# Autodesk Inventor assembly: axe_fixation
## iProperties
Shininess: 41.0
Length Units: 11269
Angle Units: 11279
Time Units: 11290
Mass Units: 11283
Length Display Precision: 3
Angle Display Precision: 2
Created: 2004-05
Part Number: axe_fixation
Document SubType Name: Assemblage
Designer: Danielc
Density: 0.0
Volumn: 0.0
Area: 0.0
PropertySet Name: Model Information
Control State: 0
Master: False
Checked Out: False
Author: Danielc
